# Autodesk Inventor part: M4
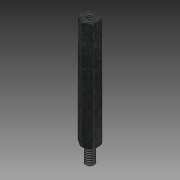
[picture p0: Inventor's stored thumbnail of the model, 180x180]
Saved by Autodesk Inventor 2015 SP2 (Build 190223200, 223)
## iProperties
Created: 2012-08
Part Number: M4
Material: Stahl
Document SubType Name: Modeling
Designer: rYan
Density: 7.85 g/cm^3
Mass: 1.74537 g
Surface Area: 3.04272 cm^2
Volume: 0.22234 cm^3
Appearance: Platte
Author: rYan
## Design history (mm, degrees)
derived "Abstandsbolzen Typ B.ipt"
feature "Volumenkörper1::Abstandsbolzen Typ B.ipt"
tag "Bezeichnung1"
node "Volumenkörper1"
other parameters: "SW" = 7, "d2" = 0, "l_" = 6, "d9" = 118 deg, "GA_" = 4, "A_" = 8, "d13" = 0, "d17" = 0.25, "d20" = 45 deg
